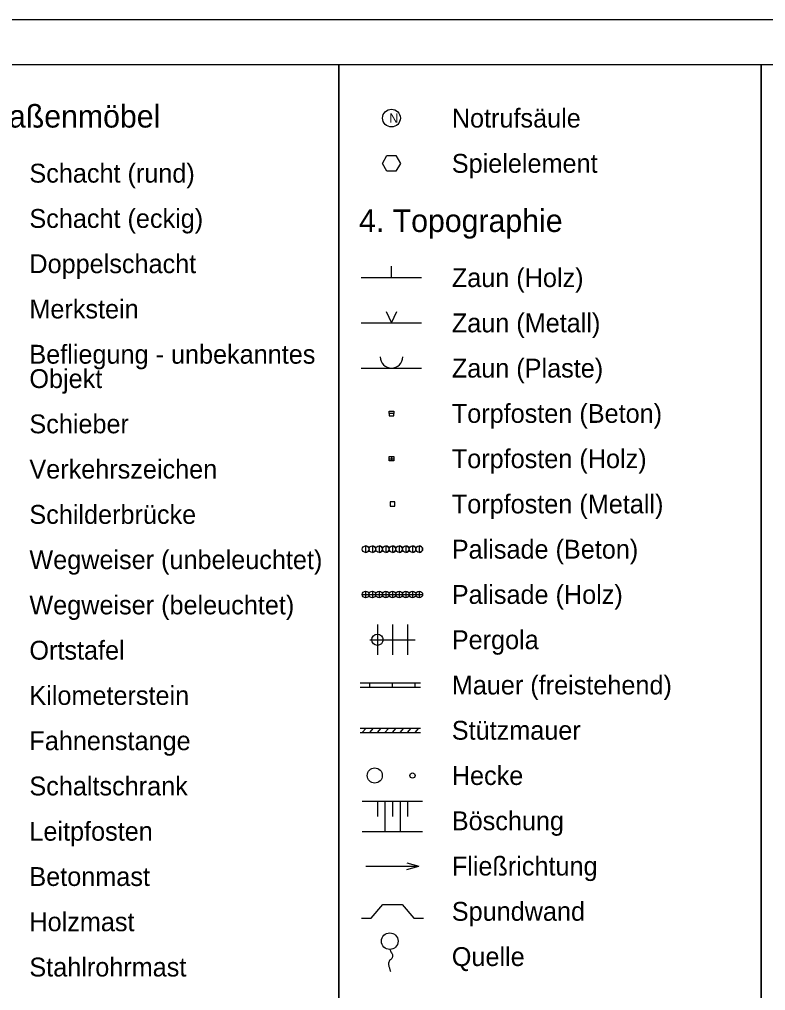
# Model space of a CAD drawing. Extents: x 679244 to 679420, y 5639809 to 5639932.
# Drawn here: x 679283.1 to 679332.6, y 5639867.3 to 5639931.7 of the extents above; entities that cross this region are included whole.
import ezdxf

# ---------------------------------------------------------------- set-up
doc = ezdxf.new("R2010")
doc.units = 0
for name, color, linetype in [('Boeschung_ok', 7, 'Continuous'), ('Boeschung_uk', 7, 'Continuous'), ('Boeschung_unbef', 7, 'Continuous'), ('Default', 7, 'Continuous'), ('Fliessrichtung', 7, 'Continuous'), ('Hecke', 7, 'Continuous'), ('Mauer_frei', 7, 'Continuous'), ('Mauer_stuetz', 7, 'Continuous'), ('Notrufsaeule', 7, 'Continuous'), ('Palisade_beton', 7, 'Continuous'), ('Palisade_holz', 7, 'Continuous'), ('Pergola', 7, 'Continuous'), ('Pfosten_beton', 7, 'Continuous'), ('Pfosten_holz', 7, 'Continuous'), ('Pfosten_metall', 7, 'Continuous'), ('Quelle', 7, 'Continuous'), ('Rahmen_1', 7, 'Continuous'), ('Spielgeraete', 7, 'Continuous'), ('Spundwand', 7, 'Continuous'), ('Zaun_holz', 7, 'Continuous'), ('Zaun_metall', 7, 'Continuous'), ('Zaun_plaste', 7, 'Continuous')]:
    doc.layers.add(name, color=color, linetype=linetype)

msp = doc.modelspace()

# ---------------------------------------------------------------- linework, layer by layer
at = {"layer": 'Boeschung_ok'}
msp.add_line((679305.844, 5639879.846), (679309.844, 5639879.846), dxfattribs=at)
at = {"layer": 'Boeschung_uk'}
msp.add_line((679305.844, 5639877.846), (679309.844, 5639877.846), dxfattribs=at)
at = {"layer": 'Boeschung_unbef'}
for p, q in [((679306.844, 5639879.846), (679306.844, 5639878.846)), ((679307.344, 5639879.846), (679307.344, 5639877.846)), ((679307.844, 5639879.846), (679307.844, 5639878.846)), ((679308.344, 5639879.846), (679308.344, 5639877.846)), ((679308.844, 5639879.846), (679308.844, 5639878.846))]:
    msp.add_line(p, q, dxfattribs=at)
at = {"layer": 'Default'}
for points in [[(679276.286, 5639808.666), (679304.286, 5639808.666), (679304.286, 5639928.666), (679276.286, 5639928.666)], [(679304.286, 5639808.666), (679332.286, 5639808.666), (679332.286, 5639928.666), (679304.286, 5639928.666)], [(679332.286, 5639808.666), (679360.286, 5639808.666), (679360.286, 5639928.666), (679332.286, 5639928.666)]]:
    msp.add_lwpolyline(points, close=True, dxfattribs=at)
at = {"layer": 'Fliessrichtung'}
for p in [(679308.789, 5639875.772), (679306.089, 5639875.555), (679308.79, 5639875.338)]:
    msp.add_line(p, (679309.6, 5639875.555), dxfattribs=at)
at = {"layer": 'Hecke'}
msp.add_line((679309.17, 5639881.556), (679309.17, 5639881.556), dxfattribs=at)
for centre, radius in [((679306.67, 5639881.555), 0.5), ((679309.17, 5639881.555), 0.175)]:
    msp.add_circle(centre, radius, dxfattribs=at)
at = {"layer": 'Mauer_frei'}
for p, q in [((679305.694, 5639887.705), (679307.094, 5639887.705)), ((679305.694, 5639887.405), (679307.094, 5639887.405)), ((679306.344, 5639887.405), (679306.344, 5639887.705)), ((679307.094, 5639887.705), (679308.594, 5639887.705)), ((679307.094, 5639887.405), (679308.594, 5639887.405)), ((679307.844, 5639887.405), (679307.844, 5639887.705)), ((679308.594, 5639887.705), (679309.694, 5639887.705)), ((679308.594, 5639887.405), (679309.694, 5639887.405)), ((679309.344, 5639887.405), (679309.344, 5639887.705))]:
    msp.add_line(p, q, dxfattribs=at)
at = {"layer": 'Mauer_stuetz'}
for p, q in [((679305.694, 5639884.705), (679306.094, 5639884.705)), ((679305.694, 5639884.405), (679306.094, 5639884.405)), ((679305.844, 5639884.405), (679306.093, 5639884.705)), ((679306.094, 5639884.705), (679306.594, 5639884.705)), ((679306.094, 5639884.405), (679306.594, 5639884.405)), ((679306.344, 5639884.405), (679306.593, 5639884.705)), ((679306.594, 5639884.705), (679307.094, 5639884.705)), ((679306.594, 5639884.405), (679307.094, 5639884.405)), ((679306.844, 5639884.405), (679307.093, 5639884.705)), ((679307.094, 5639884.705), (679307.594, 5639884.705)), ((679307.094, 5639884.405), (679307.594, 5639884.405)), ((679307.344, 5639884.405), (679307.593, 5639884.705)), ((679307.594, 5639884.705), (679308.094, 5639884.705)), ((679307.594, 5639884.405), (679308.094, 5639884.405)), ((679307.844, 5639884.405), (679308.093, 5639884.705)), ((679308.094, 5639884.705), (679308.594, 5639884.705)), ((679308.094, 5639884.405), (679308.594, 5639884.405)), ((679308.344, 5639884.405), (679308.593, 5639884.705)), ((679308.594, 5639884.705), (679309.094, 5639884.705)), ((679308.594, 5639884.405), (679309.094, 5639884.405)), ((679308.844, 5639884.405), (679309.093, 5639884.705)), ((679309.094, 5639884.705), (679309.594, 5639884.705)), ((679309.094, 5639884.405), (679309.594, 5639884.405)), ((679309.344, 5639884.405), (679309.593, 5639884.705)), ((679309.594, 5639884.705), (679309.694, 5639884.705)), ((679309.594, 5639884.405), (679309.694, 5639884.405))]:
    msp.add_line(p, q, dxfattribs=at)
at = {"layer": 'Notrufsaeule'}
msp.add_circle((679307.778, 5639925.127), 0.588, dxfattribs=at)
at = {"layer": 'Palisade_beton'}
for points in [[(679306.067, 5639896.777), (679306.067, 5639896.333)], [(679306.511, 5639896.777), (679306.511, 5639896.333)], [(679306.955, 5639896.777), (679306.955, 5639896.333)], [(679307.4, 5639896.777), (679307.4, 5639896.333)], [(679307.844, 5639896.777), (679307.844, 5639896.333)], [(679308.288, 5639896.777), (679308.288, 5639896.333)], [(679308.734, 5639896.777), (679308.734, 5639896.333)], [(679309.178, 5639896.777), (679309.178, 5639896.333)], [(679309.621, 5639896.777), (679309.621, 5639896.333)]]:
    msp.add_lwpolyline(points, dxfattribs=at)
for centre in [(679306.067, 5639896.555), (679306.511, 5639896.555), (679306.955, 5639896.555), (679307.4, 5639896.555), (679307.844, 5639896.555), (679308.288, 5639896.555), (679308.734, 5639896.555), (679309.178, 5639896.555), (679309.621, 5639896.555)]:
    msp.add_circle(centre, 0.222, dxfattribs=at)
for centre, start, end in [((679306.067, 5639896.555), 0, 90), ((679306.067, 5639896.555), 270, 360), ((679306.511, 5639896.555), 0, 90), ((679306.511, 5639896.555), 270, 0), ((679306.955, 5639896.555), 0, 90), ((679306.955, 5639896.555), 270, 0), ((679307.4, 5639896.555), 0, 90), ((679307.4, 5639896.555), 270, 360), ((679307.844, 5639896.555), 0, 90), ((679307.844, 5639896.555), 270, 0), ((679308.288, 5639896.555), 0, 90), ((679308.288, 5639896.555), 270, 0), ((679308.734, 5639896.555), 0, 90), ((679308.734, 5639896.555), 270, 360), ((679309.178, 5639896.555), 0, 90), ((679309.178, 5639896.555), 270, 0), ((679309.621, 5639896.555), 0, 90), ((679309.621, 5639896.555), 270, 0)]:
    msp.add_arc(centre, 0.222, start, end, dxfattribs=at)
at = {"layer": 'Palisade_holz'}
for p, q in [((679306.067, 5639893.777), (679306.067, 5639893.333)), ((679306.511, 5639893.777), (679306.511, 5639893.333)), ((679306.955, 5639893.777), (679306.955, 5639893.333)), ((679307.4, 5639893.777), (679307.4, 5639893.333)), ((679307.844, 5639893.777), (679307.844, 5639893.333)), ((679308.288, 5639893.777), (679308.288, 5639893.333)), ((679308.734, 5639893.777), (679308.734, 5639893.333)), ((679309.178, 5639893.777), (679309.178, 5639893.333)), ((679309.621, 5639893.777), (679309.621, 5639893.333))]:
    msp.add_line(p, q, dxfattribs=at)
for points in [[(679305.845, 5639893.555), (679306.289, 5639893.555)], [(679306.289, 5639893.555), (679306.733, 5639893.555)], [(679306.733, 5639893.555), (679307.177, 5639893.555)], [(679307.178, 5639893.555), (679307.622, 5639893.555)], [(679307.622, 5639893.555), (679308.066, 5639893.555)], [(679308.066, 5639893.555), (679308.51, 5639893.555)], [(679308.512, 5639893.555), (679308.956, 5639893.555)], [(679308.956, 5639893.555), (679309.399, 5639893.555)], [(679309.399, 5639893.555), (679309.843, 5639893.555)]]:
    msp.add_lwpolyline(points, dxfattribs=at)
for centre in [(679306.067, 5639893.555), (679306.511, 5639893.555), (679306.955, 5639893.555), (679307.4, 5639893.555), (679307.844, 5639893.555), (679308.288, 5639893.555), (679308.734, 5639893.555), (679309.178, 5639893.555), (679309.621, 5639893.555)]:
    msp.add_circle(centre, 0.222, dxfattribs=at)
at = {"layer": 'Pergola'}
for p, q in [((679306.844, 5639891.555), (679306.844, 5639889.555)), ((679307.844, 5639891.555), (679307.844, 5639889.555)), ((679308.844, 5639891.555), (679308.844, 5639889.555)), ((679306.344, 5639890.555), (679309.344, 5639890.555))]:
    msp.add_line(p, q, dxfattribs=at)
msp.add_circle((679306.844, 5639890.555), 0.375, dxfattribs=at)
at = {"layer": 'Pfosten_beton'}
for points in [[(679307.629, 5639905.703), (679307.927, 5639905.703), (679307.927, 5639905.554), (679307.629, 5639905.554)], [(679307.928, 5639905.405), (679307.928, 5639905.554), (679307.629, 5639905.554), (679307.629, 5639905.405)]]:
    msp.add_lwpolyline(points, close=True, dxfattribs=at)
at = {"layer": 'Pfosten_holz'}
for p, q in [((679307.629, 5639902.554), (679307.928, 5639902.554)), ((679307.778, 5639902.703), (679307.778, 5639902.405))]:
    msp.add_line(p, q, dxfattribs=at)
msp.add_lwpolyline([(679307.629, 5639902.703), (679307.928, 5639902.703), (679307.928, 5639902.405), (679307.629, 5639902.405)], close=True, dxfattribs=at)
at = {"layer": 'Pfosten_metall'}
msp.add_lwpolyline([(679307.994, 5639899.406), (679307.993, 5639899.704), (679307.695, 5639899.704), (679307.695, 5639899.406)], close=True, dxfattribs=at)
at = {"layer": 'Quelle'}
msp.add_circle((679307.663, 5639870.578), 0.55, dxfattribs=at)
for points in [[(679307.669, 5639870.026), (679307.703, 5639869.929), (679307.732, 5639869.883), (679307.76, 5639869.838), (679307.783, 5639869.804)], [(679307.698, 5639869.343), (679307.686, 5639869.337), (679307.658, 5639869.309), (679307.624, 5639869.246), (679307.607, 5639869.195), (679307.589, 5639869.138), (679307.586, 5639869.125)], [(679307.783, 5639869.804), (679307.811, 5639869.77), (679307.84, 5639869.69), (679307.846, 5639869.599), (679307.834, 5639869.502), (679307.794, 5639869.434), (679307.755, 5639869.394), (679307.698, 5639869.343)], [(679307.589, 5639869.138), (679307.584, 5639869.064), (679307.595, 5639868.967), (679307.612, 5639868.899), (679307.641, 5639868.802), (679307.663, 5639868.717), (679307.686, 5639868.637), (679307.709, 5639868.569)]]:
    msp.add_spline(points, degree=3, dxfattribs=at)
at = {"layer": 'Rahmen_1'}
msp.add_lwpolyline([(679419.991, 5639808.515), (679243.507, 5639808.515), (679243.507, 5639931.667), (679419.991, 5639931.667)], close=True, dxfattribs=at)
at = {"layer": 'Spielgeraete'}
for p, q in [((679307.178, 5639922.127), (679307.478, 5639922.646)), ((679307.478, 5639921.607), (679307.178, 5639922.127)), ((679307.478, 5639922.646), (679308.078, 5639922.646)), ((679308.078, 5639922.646), (679308.378, 5639922.127)), ((679308.378, 5639922.127), (679308.078, 5639921.607)), ((679308.078, 5639921.607), (679307.478, 5639921.607))]:
    msp.add_line(p, q, dxfattribs=at)
at = {"layer": 'Spundwand'}
msp.add_lwpolyline([(679305.793, 5639872.095), (679306.433, 5639872.095), (679307.204, 5639873.014), (679308.484, 5639873.014), (679309.255, 5639872.095), (679309.895, 5639872.095)], dxfattribs=at)
at = {"layer": 'Zaun_holz'}
for p, q in [((679307.778, 5639914.555), (679307.778, 5639915.305)), ((679305.778, 5639914.554), (679309.778, 5639914.554))]:
    msp.add_line(p, q, dxfattribs=at)
at = {"layer": 'Zaun_metall'}
msp.add_line((679305.778, 5639911.554), (679309.778, 5639911.554), dxfattribs=at)
msp.add_lwpolyline([(679307.417, 5639912.301), (679307.778, 5639911.554), (679308.139, 5639912.301)], dxfattribs=at)
at = {"layer": 'Zaun_plaste'}
msp.add_line((679305.778, 5639908.554), (679309.778, 5639908.554), dxfattribs=at)
msp.add_arc((679307.778, 5639909.304), 0.75, 180, 0, dxfattribs=at)

# ---------------------------------------------------------------- texts
at = {"layer": 'Default'}
for s, height, p in [('3. Straßenmöbel', 1.5, (679277.628, 5639924.5)), ('Notrufsäule', 1.25, (679311.778, 5639924.502)), ('Spielelement', 1.25, (679311.778, 5639921.502)), ('Schacht (rund)', 1.25, (679283.778, 5639920.851)), ('Schacht (eckig)', 1.25, (679283.778, 5639917.851)), ('4. Topographie', 1.5, (679305.628, 5639917.579)), ('Doppelschacht', 1.25, (679283.778, 5639914.851)), ('Zaun (Holz)', 1.25, (679311.778, 5639913.93)), ('Merkstein', 1.25, (679283.778, 5639911.851)), ('Zaun (Metall)', 1.25, (679311.778, 5639910.93)), ('Befliegung - unbekanntes ', 1.25, (679283.778, 5639908.851)), ('Zaun (Plaste)', 1.25, (679311.778, 5639907.93)), ('Objekt', 1.25, (679283.778, 5639907.237)), ('Torpfosten (Beton)', 1.25, (679311.778, 5639904.93)), ('Schieber', 1.25, (679283.778, 5639904.237)), ('Torpfosten (Holz)', 1.25, (679311.778, 5639901.93)), ('Verkehrszeichen', 1.25, (679283.778, 5639901.237)), ('Torpfosten (Metall)', 1.25, (679311.778, 5639898.93)), ('Schilderbrücke', 1.25, (679283.778, 5639898.237)), ('Palisade (Beton)', 1.25, (679311.778, 5639895.93)), ('Wegweiser (unbeleuchtet)', 1.25, (679283.778, 5639895.237)), ('Palisade (Holz)', 1.25, (679311.778, 5639892.93)), ('Wegweiser (beleuchtet)', 1.25, (679283.778, 5639892.237)), ('Pergola', 1.25, (679311.778, 5639889.93)), ('Ortstafel', 1.25, (679283.778, 5639889.237)), ('Mauer (freistehend)', 1.25, (679311.778, 5639886.93)), ('Kilometerstein', 1.25, (679283.778, 5639886.237)), ('Stützmauer', 1.25, (679311.778, 5639883.93)), ('Fahnenstange', 1.25, (679283.778, 5639883.237)), ('Hecke', 1.25, (679311.778, 5639880.93)), ('Schaltschrank', 1.25, (679283.778, 5639880.237)), ('Böschung ', 1.25, (679311.778, 5639877.93)), ('Leitpfosten', 1.25, (679283.778, 5639877.237)), ('Fließrichtung', 1.25, (679311.778, 5639874.93)), ('Betonmast', 1.25, (679283.778, 5639874.237)), ('Spundwand', 1.25, (679311.778, 5639871.93)), ('Holzmast', 1.25, (679283.778, 5639871.237)), ('Quelle', 1.25, (679311.778, 5639868.93)), ('Stahlrohrmast', 1.25, (679283.778, 5639868.237))]:
    msp.add_text(s, height=height, dxfattribs=at).set_placement(p)
at = {"layer": 'Notrufsaeule'}
msp.add_text('N', height=0.625, dxfattribs=at).set_placement((679307.629, 5639924.814))

doc.saveas('drawing.dxf')
